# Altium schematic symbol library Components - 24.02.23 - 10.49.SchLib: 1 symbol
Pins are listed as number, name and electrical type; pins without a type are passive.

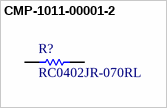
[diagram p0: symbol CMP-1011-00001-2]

## CMP-1011-00001-2
designator R?, comment RC0402JR-070RL
Manufacturer: Yageo / Phycomp
footprint RESC1005X40X25ML05T10 (Chip Resistor, 2-Leads, Body 1.00x0.50mm, IPC Low Density)
footprint RESC1005X40X25LL05T10 (Chip Resistor, 2-Leads, Body 1.00x0.50mm, IPC High Density)
footprint RESC1005X40X25NL05T10 (Chip Resistor, 2-Leads, Body 1.00x0.50mm, IPC Medium Density)
pins: 1, 2
1 alternate drawing of the same symbol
